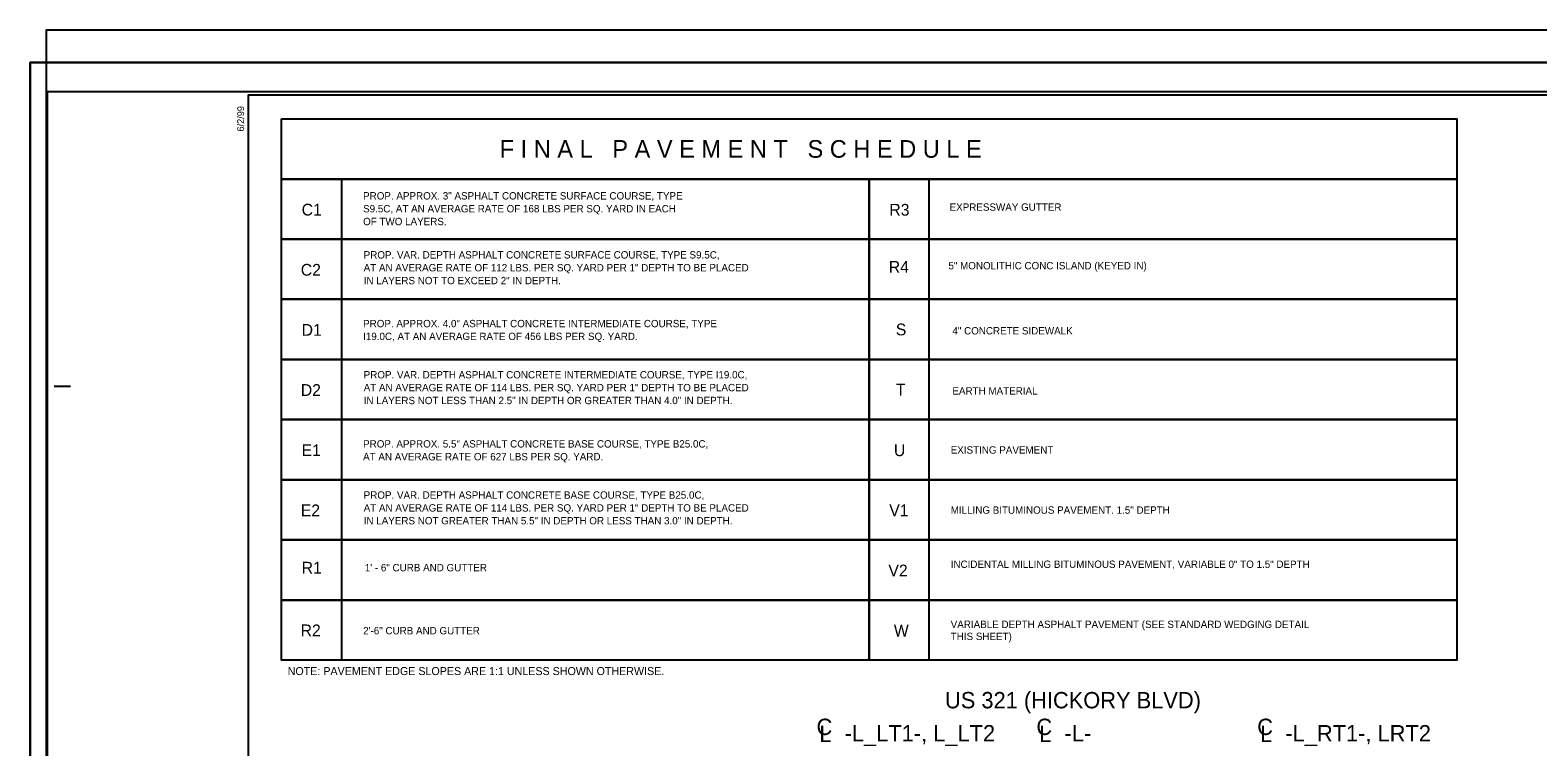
# Model space of a CAD drawing. Extents: x 2294342 to 2294901, y 719427 to 719941.
# Drawn here: x 2294454.5 to 2294685.4, y 719831.5 to 719941.1 of the extents above; entities that cross this region are included whole.
import ezdxf

# ---------------------------------------------------------------- set-up
doc = ezdxf.new("R2010")
doc.units = 0
for name, color, linetype in [('Default', 7, 'Continuous'), ('Old_Level_2', 7, 'Continuous'), ('Old_Level_3', 7, 'Continuous'), ('Prop Pavement Schedule Description CELL', 7, 'Continuous'), ('Sheet Plot Border Inside CELL', 7, 'Continuous'), ('Sheet Plot Border Outside CELL', 7, 'Continuous'), ('Sheet Typical CELL', 7, 'Continuous')]:
    doc.layers.add(name, color=color, linetype=linetype)

msp = doc.modelspace()

# ---------------------------------------------------------------- linework, layer by layer
at = {"layer": 'Default'}
msp.add_line((2294454.52, 719936.17), (2294794.52, 719936.17), dxfattribs=at)
msp.add_lwpolyline([(2294454.52, 719936.17), (2294794.52, 719936.17), (2294794.52, 719716.17), (2294454.52, 719716.17)], close=True, dxfattribs=at)
msp.add_lwpolyline([(2294454.52, 719936.17), (2294794.52, 719936.17), (2294794.52, 719716.17), (2294454.52, 719716.17)], close=True, dxfattribs=at)
at = {"layer": 'Prop Pavement Schedule Description CELL'}
msp.add_lwpolyline([(2294493.04, 719927.56), (2294673.04, 719927.56), (2294673.04, 719918.35), (2294493.04, 719918.35)], close=True, dxfattribs=at)
for points in [[(2294502.24, 719909.15), (2294493.04, 719909.15), (2294493.04, 719918.35), (2294583.04, 719918.35), (2294583.04, 719909.15), (2294502.24, 719909.15), (2294502.24, 719918.35)], [(2294592.24, 719909.15), (2294583.04, 719909.15), (2294583.04, 719918.35), (2294673.04, 719918.35), (2294673.04, 719909.15), (2294592.24, 719909.15), (2294592.24, 719918.35)], [(2294502.24, 719899.95), (2294493.04, 719899.95), (2294493.04, 719909.15), (2294583.04, 719909.15), (2294583.04, 719899.95), (2294502.24, 719899.95), (2294502.24, 719909.15)], [(2294592.24, 719899.95), (2294583.04, 719899.95), (2294583.04, 719909.15), (2294673.04, 719909.15), (2294673.04, 719899.95), (2294592.24, 719899.95), (2294592.24, 719909.15)], [(2294592.24, 719899.95), (2294583.04, 719899.95), (2294583.04, 719909.15), (2294673.04, 719909.15), (2294673.04, 719899.95), (2294592.24, 719899.95), (2294592.24, 719909.15)], [(2294502.24, 719890.74), (2294493.04, 719890.74), (2294493.04, 719899.95), (2294583.04, 719899.95), (2294583.04, 719890.74), (2294502.24, 719890.74), (2294502.24, 719899.95)], [(2294592.24, 719890.74), (2294583.04, 719890.74), (2294583.04, 719899.95), (2294673.04, 719899.95), (2294673.04, 719890.74), (2294592.24, 719890.74), (2294592.24, 719899.95)], [(2294502.24, 719881.54), (2294493.04, 719881.54), (2294493.04, 719890.74), (2294583.04, 719890.74), (2294583.04, 719881.54), (2294502.24, 719881.54), (2294502.24, 719890.74)], [(2294592.24, 719881.54), (2294583.04, 719881.54), (2294583.04, 719890.74), (2294673.04, 719890.74), (2294673.04, 719881.54), (2294592.24, 719881.54), (2294592.24, 719890.74)], [(2294502.24, 719872.33), (2294493.04, 719872.33), (2294493.04, 719881.54), (2294583.04, 719881.54), (2294583.04, 719872.33), (2294502.24, 719872.33), (2294502.24, 719881.54)], [(2294592.24, 719872.33), (2294583.04, 719872.33), (2294583.04, 719881.54), (2294673.04, 719881.54), (2294673.04, 719872.33), (2294592.24, 719872.33), (2294592.24, 719881.54)], [(2294502.24, 719863.13), (2294493.04, 719863.13), (2294493.04, 719872.33), (2294583.04, 719872.33), (2294583.04, 719863.13), (2294502.24, 719863.13), (2294502.24, 719872.33)], [(2294592.24, 719863.13), (2294583.04, 719863.13), (2294583.04, 719872.33), (2294673.04, 719872.33), (2294673.04, 719863.13), (2294592.24, 719863.13), (2294592.24, 719872.33)], [(2294502.24, 719853.92), (2294493.04, 719853.92), (2294493.04, 719863.13), (2294583.04, 719863.13), (2294583.04, 719853.92), (2294502.24, 719853.92), (2294502.24, 719863.13)], [(2294592.24, 719853.92), (2294583.04, 719853.92), (2294583.04, 719863.13), (2294673.04, 719863.13), (2294673.04, 719853.92), (2294592.24, 719853.92), (2294592.24, 719863.13)], [(2294502.24, 719844.72), (2294493.04, 719844.72), (2294493.04, 719853.92), (2294583.04, 719853.92), (2294583.04, 719844.72), (2294502.24, 719844.72), (2294502.24, 719853.92)], [(2294592.24, 719844.72), (2294583.04, 719844.72), (2294583.04, 719853.92), (2294673.04, 719853.92), (2294673.04, 719844.72), (2294592.24, 719844.72), (2294592.24, 719853.92)]]:
    msp.add_lwpolyline(points, dxfattribs=at)
at = {"layer": 'Sheet Plot Border Inside CELL'}
msp.add_lwpolyline([(2294790.42, 719931.68), (2294457.12, 719931.68), (2294457.12, 719720.66), (2294790.42, 719720.66)], close=True, dxfattribs=at)
at = {"layer": 'Sheet Plot Border Outside CELL'}
for points in [[(2294793.79, 719941.13), (2294456.99, 719941.13), (2294456.99, 719721.13), (2294793.79, 719721.13)], [(2294794.52, 719936.17), (2294454.52, 719936.17), (2294454.52, 719716.17), (2294794.52, 719716.17)]]:
    msp.add_lwpolyline(points, close=True, dxfattribs=at)
at = {"layer": 'Sheet Typical CELL'}
msp.add_line((2294458.22, 719886.67), (2294460.72, 719886.67), dxfattribs=at)
msp.add_lwpolyline([(2294787.92, 719931.17), (2294487.92, 719931.17), (2294487.92, 719721.17), (2294787.92, 719721.17)], close=True, dxfattribs=at)

# ---------------------------------------------------------------- texts
at = {"layer": 'Old_Level_2'}
for s, rotation, p in [('C', 360, (2294574.97, 719833.27)), ('L', 359.9469, (2294575.4, 719832.2)), ('C', 360, (2294608.64, 719833.27)), ('L', 359.9469, (2294609.08, 719832.2)), ('C', 360, (2294642.47, 719833.27)), ('L', 359.9469, (2294642.9, 719832.2))]:
    msp.add_text(s, height=2.5, rotation=rotation, dxfattribs=at).set_placement(p)
at = {"layer": 'Old_Level_3'}
for s, p in [('US 321 (HICKORY BLVD)', (2294594.65, 719837.35)), ('-L_LT1-, L_LT2', (2294579.28, 719832.29)), ('-L-', (2294612.95, 719832.29)), ('-L_RT1-, LRT2', (2294646.78, 719832.29))]:
    msp.add_text(s, height=2.5, rotation=0, dxfattribs=at).set_placement(p)
at = {"layer": 'Prop Pavement Schedule Description CELL'}
for s, height, p in [('F I N A L   P A V E M E N T   S C H E D U L E', 2.7, (2294526.44, 719921.61)), ('PROP. APPROX. 3" ASPHALT CONCRETE SURFACE COURSE, TYPE ', 1.125, (2294505.52, 719915.22)), ('C1', 1.8, (2294496.11, 719912.77)), ('S9.5C, AT AN AVERAGE RATE OF 168 LBS PER SQ. YARD IN EACH', 1.125, (2294505.52, 719913.25)), ('EXPRESSWAY GUTTER', 1.125, (2294595.35, 719913.5)), ('OF TWO LAYERS.', 1.125, (2294505.52, 719911.29)), ('PROP. VAR. DEPTH ASPHALT CONCRETE SURFACE COURSE, TYPE S9.5C,', 1.125, (2294505.61, 719906.19)), ('5" MONOLITHIC CONC ISLAND (KEYED IN)', 1.125, (2294595.17, 719904.53)), ('C2', 1.8, (2294495.98, 719903.56)), ('AT AN AVERAGE RATE OF 112 LBS. PER SQ. YARD PER 1" DEPTH TO BE PLACED', 1.125, (2294505.61, 719904.22)), ('IN LAYERS NOT TO EXCEED 2" IN DEPTH.', 1.125, (2294505.61, 719902.25)), ('PROP. APPROX. 4.0" ASPHALT CONCRETE INTERMEDIATE COURSE, TYPE ', 1.125, (2294505.52, 719895.67)), ('D1', 1.8, (2294496.11, 719894.36)), ('I19.0C, AT AN AVERAGE RATE OF 456 LBS PER SQ. YARD.', 1.125, (2294505.52, 719893.71)), ('S', 1.8, (2294587.12, 719894.43)), ('4" CONCRETE SIDEWALK', 1.125, (2294595.78, 719894.57)), ('PROP. VAR. DEPTH ASPHALT CONCRETE INTERMEDIATE COURSE, TYPE I19.0C,', 1.125, (2294505.61, 719887.84)), ('D2', 1.8, (2294495.98, 719885.16)), ('AT AN AVERAGE RATE OF 114 LBS. PER SQ. YARD PER 1" DEPTH TO BE PLACED', 1.125, (2294505.61, 719885.87)), ('IN LAYERS NOT LESS THAN 2.5" IN DEPTH OR GREATER THAN 4.0" IN DEPTH.', 1.125, (2294505.61, 719883.9)), ('T', 1.8, (2294587.12, 719885.22)), ('EARTH MATERIAL', 1.125, (2294595.78, 719885.37)), ('PROP. APPROX. 5.5" ASPHALT CONCRETE BASE COURSE, TYPE B25.0C, ', 1.125, (2294505.52, 719877.26)), ('E1', 1.8, (2294496.11, 719875.95)), ('AT AN AVERAGE RATE OF 627 LBS PER SQ. YARD.', 1.125, (2294505.52, 719875.3)), ('U', 1.8, (2294586.82, 719875.95)), ('EXISTING PAVEMENT', 1.125, (2294595.52, 719876.33)), ('PROP. VAR. DEPTH ASPHALT CONCRETE BASE COURSE, TYPE B25.0C,', 1.125, (2294505.61, 719869.43)), ('E2', 1.8, (2294495.98, 719866.75)), ('AT AN AVERAGE RATE OF 114 LBS. PER SQ. YARD PER 1" DEPTH TO BE PLACED', 1.125, (2294505.61, 719867.46)), ('IN LAYERS NOT GREATER THAN 5.5" IN DEPTH OR LESS THAN 3.0" IN DEPTH.', 1.125, (2294505.61, 719865.5)), ('V1', 1.8, (2294586.11, 719866.75)), ('MILLING BITUMINOUS PAVEMENT. 1.5" DEPTH', 1.125, (2294595.52, 719867.13)), ('INCIDENTAL MILLING BITUMINOUS PAVEMENT, VARIABLE 0" TO 1.5" DEPTH', 1.125, (2294595.52, 719858.84)), ('V2', 1.8, (2294585.98, 719857.54)), ('VARIABLE DEPTH ASPHALT PAVEMENT (SEE STANDARD WEDGING DETAIL', 1.125, (2294595.52, 719849.64)), ('2\'-6" CURB AND GUTTER', 1.125, (2294505.53, 719848.67)), ('W', 1.8, (2294586.82, 719848.34)), ('THIS SHEET)', 1.125, (2294595.52, 719847.8)), ('NOTE: PAVEMENT EDGE SLOPES ARE 1:1 UNLESS SHOWN OTHERWISE.', 1.2244, (2294493.97, 719842.44))]:
    msp.add_text(s, height=height, rotation=0, dxfattribs=at).set_placement(p)
for s, height, p in [('R3', 1.8, (2294586.13, 719912.75)), ('R4', 1.8, (2294586.04, 719904.01)), ('R1', 1.8, (2294496.12, 719857.97)), ('1\' - 6" CURB AND GUTTER', 1.125, (2294505.78, 719858.32)), ('R2', 1.8, (2294495.95, 719848.38))]:
    msp.add_text(s, height=height, dxfattribs=at).set_placement(p)
at = {"layer": 'Sheet Typical CELL'}
msp.add_text('6/2/99', height=1.05, rotation=90, dxfattribs=at).set_placement((2294487.29, 719925.62))

doc.saveas('drawing.dxf')
